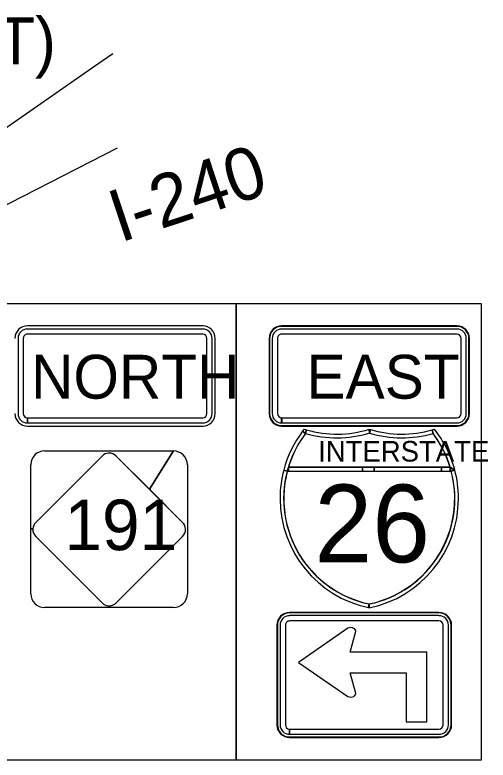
# Model space of a CAD drawing. Extents: x 886234 to 968767, y 455416 to 684046.
# Drawn here: x 919925 to 921059, y 516776 to 518560 of the extents above; entities that cross this region are included whole.
import ezdxf

# ---------------------------------------------------------------- set-up
doc = ezdxf.new("R2010")
doc.units = 0
for name, color, linetype in [('TC CONSTRUCTION PROPOSED ROADWAY SHADE', 7, 'Continuous'), ('TC DEV SIGN BLACK 239', 7, 'Continuous'), ('TC DEV SIGN BLACK ZERO', 7, 'Continuous'), ('TC DEV SIGN WHITE', 7, 'Continuous'), ('TC LABEL TEXT', 7, 'Continuous')]:
    doc.layers.add(name, color=color, linetype=linetype)

msp = doc.modelspace()

# ---------------------------------------------------------------- linework, layer by layer
at = {"layer": 'TC CONSTRUCTION PROPOSED ROADWAY SHADE'}
msp.add_lwpolyline([(920455, 517868.9), (921042.7, 517868.9), (921042.7, 516775.8), (920455, 516775.8)], close=True, dxfattribs=at)
at = {"layer": 'TC DEV SIGN BLACK 239'}
for p, q in [((920375.2, 517808), (919955.2, 517808)), ((920375.2, 517808), (919955.2, 517808)), ((920984.3, 517808), (920564.3, 517808)), ((919932.7, 517785.5), (919932.7, 517605.5)), ((919932.7, 517785.5), (919932.7, 517605.5)), ((919945.2, 517785.5), (919945.2, 517605.5)), ((919945.2, 517785.5), (919945.2, 517605.5)), ((920375.2, 517795.5), (919955.2, 517795.5)), ((920375.2, 517795.5), (919955.2, 517795.5)), ((920385.2, 517605.5), (920385.2, 517785.5)), ((920385.2, 517605.5), (920385.2, 517785.5)), ((920397.7, 517605.5), (920397.7, 517785.5)), ((920397.7, 517605.5), (920397.7, 517785.5)), ((920541.8, 517785.5), (920541.8, 517605.5)), ((920554.3, 517785.5), (920554.3, 517605.5)), ((920984.3, 517795.5), (920564.3, 517795.5)), ((920994.3, 517605.5), (920994.3, 517785.5)), ((921006.8, 517605.5), (921006.8, 517785.5)), ((919955.2, 517583), (919955.2, 517595.5)), ((919955.2, 517583), (919955.2, 517595.5)), ((919955.3, 517595.5), (920375.2, 517595.5)), ((919955.3, 517595.5), (919955.3, 517583)), ((919955.3, 517595.5), (920375.2, 517595.5)), ((919955.3, 517595.5), (919955.3, 517583)), ((920564.3, 517583), (920564.3, 517595.5)), ((920564.4, 517595.5), (920984.3, 517595.5)), ((920564.4, 517595.5), (920564.4, 517583)), ((919955.3, 517583), (920375.2, 517583)), ((919955.3, 517583), (920375.2, 517583)), ((920564.4, 517583), (920984.3, 517583)), ((919996.5, 517516.1), (920150.9, 517516.1)), ((919996.5, 517516.1), (919996.5, 517516.1)), ((919996.5, 517516.1), (920305.3, 517516.1)), ((919996.5, 517516.1), (919996.5, 517516.1)), ((920150.9, 517516.1), (920305.3, 517516.1)), ((920247.6, 517424.4), (920305.3, 517516.1)), ((920134.1, 517503.8), (919975.3, 517345)), ((919963.4, 517329.5), (919963.4, 517483)), ((919963.4, 517329.5), (919963.4, 517483)), ((920338.4, 517483), (920338.4, 517174.2)), ((920338.4, 517483), (920338.4, 517174.2)), ((920327, 517345), (920247.6, 517424.4)), ((919968.3, 517329.5), (919963.4, 517329.5)), ((919963.4, 517329.4), (919968.3, 517329.4)), ((919963.4, 517174.2), (919963.4, 517329.4)), ((919963.4, 517174.2), (919963.4, 517329.4)), ((919975.3, 517311), (920134.1, 517152.2)), ((920168.2, 517152.2), (920327, 517311)), ((920305.3, 517141.1), (919996.5, 517141.1)), ((920150.9, 517141.1), (919996.5, 517141.1)), ((920305.3, 517141.1), (920150.9, 517141.1)), ((920941.2, 517121.7), (920583.4, 517121.7)), ((920941.2, 517109), (920583.4, 517109)), ((920560.6, 517098.8), (920560.6, 516860.3)), ((920573.3, 517098.8), (920573.3, 516860.3)), ((920723.1, 517091.5), (920604.5, 517009.8)), ((920951.3, 516860.3), (920951.3, 517098.8)), ((920964, 516860.3), (920964, 517098.8)), ((920728.3, 517034.2), (920741.6, 517081.5)), ((920912.5, 517034.2), (920728.3, 517034.2)), ((920912.5, 516867.2), (920912.5, 517034.2)), ((920604.5, 517009.8), (920723.1, 516928.2)), ((920741.6, 516938.1), (920728.2, 516984.6)), ((920728.2, 516984.6), (920863, 516984.6)), ((920863, 516984.6), (920863, 516867.2)), ((920863, 516867.2), (920912.5, 516867.2)), ((920583.4, 516837.5), (920583.4, 516850.2)), ((920583.5, 516850.2), (920941.2, 516850.2)), ((920583.5, 516850.2), (920583.5, 516837.5)), ((920583.5, 516837.5), (920941.2, 516837.5))]:
    msp.add_line(p, q, dxfattribs=at)
msp.add_lwpolyline([(920305.3, 517516.1), (920247.6, 517424.4), (920168.2, 517503.8)], dxfattribs=at)
for centre, radius, start, end in [((919996.5, 517483), 33.1, 90, 180), ((919996.5, 517483), 33.1, 90, 180), ((920305.3, 517483), 33.1, 360, 90), ((920305.3, 517483), 33.1, 360, 90), ((920151.1, 517486.8), 24.1, 93.2102, 135), ((920151.1, 517486.8), 24.1, 45, 93.0763), ((919992.3, 517328), 24.1, 135, 176.407), ((920310, 517328), 24.1, 1.9293, 45), ((919992.3, 517328), 24.1, 176.5595, 225), ((920310, 517328), 24.1, 315, 1.7382), ((919996.5, 517174.2), 33.1, 180, 270), ((919996.5, 517174.2), 33.1, 180, 270), ((920305.3, 517174.2), 33.1, 270, 360), ((920305.3, 517174.2), 33.1, 270, 360), ((920151.1, 517169.2), 24.1, 225, 265.0473), ((920151.1, 517169.2), 24.1, 265.1815, 315)]:
    msp.add_arc(centre, radius, start, end, dxfattribs=at)
for centre, major_axis, ratio, start_param, end_param in [((919955.2, 517785.5), (22.5, 0), 0.999865, 1.570796, 3.141593), ((919955.2, 517785.5), (22.5, 0), 0.999865, 1.570796, 3.141593), ((920375.2, 517785.5), (22.5, 0), 0.999865, 0, 1.570796), ((920375.2, 517785.5), (22.5, 0), 0.999865, 0, 1.570796), ((920564.3, 517785.5), (22.5, 0), 0.999865, 1.570796, 3.141593), ((920984.3, 517785.5), (22.5, 0), 0.999865, 0, 1.570796), ((919955.2, 517785.5), (10, 0), 0.999865, 1.570796, 3.141593), ((919955.2, 517785.5), (10, 0), 0.999865, 1.570796, 3.141593), ((920375.2, 517785.5), (10, 0), 0.999865, 0, 1.570796), ((920375.2, 517785.5), (10, 0), 0.999865, 0, 1.570796), ((920564.3, 517785.5), (10, 0), 0.999865, 1.570796, 3.141593), ((920984.3, 517785.5), (10, 0), 0.999865, 0, 1.570796), ((919955.2, 517605.5), (22.5, 0), 0.999865, 3.141593, 4.712389), ((919955.2, 517605.5), (22.5, 0), 0.999865, 3.141593, 4.712389), ((919955.2, 517605.5), (10, 0), 0.999865, 3.141593, 4.712389), ((919955.2, 517605.5), (10, 0), 0.999865, 3.141593, 4.712389), ((920375.2, 517605.5), (22.5, 0), 0.999865, 4.712389, 6.283185), ((920375.2, 517605.5), (10, 0), 0.999865, 4.712389, 6.283185), ((920375.2, 517605.5), (22.5, 0), 0.999865, 4.712389, 6.283185), ((920375.2, 517605.5), (10, 0), 0.999865, 4.712389, 6.283185), ((920564.3, 517605.5), (22.5, 0), 0.999865, 3.141593, 4.712389), ((920564.3, 517605.5), (10, 0), 0.999865, 3.141593, 4.712389), ((920984.3, 517605.5), (22.5, 0), 0.999865, 4.712389, 6.283185), ((920984.3, 517605.5), (10, 0), 0.999865, 4.712389, 6.283185), ((920583.4, 517098.8), (22.8, 0), 0.999865, 1.570796, 3.141593), ((920583.4, 517098.8), (10.1, 0), 0.999865, 1.570796, 3.141593), ((920941.2, 517098.8), (22.8, 0), 0.999865, 0, 1.570796), ((920941.2, 517098.8), (10.1, 0), 0.999865, 0, 1.570796), ((920730, 517084.2), (-12.2, 0), 0.720018, 2.830617, 5.313577), ((920730, 516935.4), (-12.2, 0), 0.720018, 0.96961, 3.452569), ((920583.4, 516860.3), (22.8, 0), 0.999865, 3.141593, 4.712389), ((920583.4, 516860.3), (10.1, 0), 0.999865, 3.141593, 4.712389), ((920941.2, 516860.3), (22.8, 0), 0.999865, 4.712389, 6.283185), ((920941.2, 516860.3), (10.1, 0), 0.999865, 4.712389, 6.283185)]:
    msp.add_ellipse(centre, major_axis=major_axis, ratio=ratio, start_param=start_param, end_param=end_param, dxfattribs=at)
at = {"layer": 'TC DEV SIGN BLACK ZERO'}
for p, q in [((920984.3, 517815.5), (920564.3, 517815.5)), ((920564.3, 517814.2), (920564.3, 517814.3)), ((920984.3, 517814.2), (920564.3, 517814.3)), ((920984.3, 517814.2), (920984.3, 517814.2)), ((920534.2, 517785.5), (920534.2, 517605.5)), ((920535.5, 517785.5), (920535.5, 517605.5)), ((920535.5, 517785.5), (920535.5, 517785.5)), ((921013.1, 517785.5), (921013.1, 517785.5)), ((921013.1, 517605.5), (921013.1, 517785.5)), ((921014.3, 517605.5), (921014.3, 517785.5)), ((920535.5, 517605.5), (920535.5, 517605.5)), ((921013.1, 517605.5), (921013.1, 517605.5)), ((920564.3, 517575.5), (920564.3, 517576.8)), ((920564.3, 517576.8), (920564.3, 517576.7)), ((920564.3, 517576.8), (920984.3, 517576.8)), ((920564.3, 517576.8), (920564.3, 517575.5)), ((920564.3, 517575.5), (920984.3, 517575.5)), ((920984.3, 517576.7), (920984.3, 517576.8)), ((920621.4, 517557.7), (920623.8, 517566.3)), ((920774.5, 517558.7), (920774.2, 517568)), ((920774.5, 517559.4), (920774.2, 517568)), ((920924.7, 517566.3), (920927.1, 517557.7)), ((920577.9, 517467.9), (920970.6, 517467.9)), ((920577.9, 517467.9), (920580.4, 517467.9)), ((920580.4, 517476.8), (920968.1, 517476.8)), ((920757.9, 517476.8), (920580.4, 517476.8)), ((920580.4, 517467.9), (920757.9, 517467.9)), ((920786.1, 517476.8), (920757.9, 517476.8)), ((920757.9, 517467.9), (920786.1, 517467.9)), ((920947.1, 517476.8), (920786.1, 517476.8)), ((920786.1, 517467.9), (920947.1, 517467.9)), ((920968.1, 517476.8), (920947.1, 517476.8)), ((920947.1, 517467.9), (920968.1, 517467.9)), ((920979.2, 517470.2), (920968.1, 517476.8)), ((920970.4, 517468.6), (920968.1, 517467.9)), ((920968.1, 517467.9), (920970.6, 517467.9)), ((920560.5, 517403.6), (920560.5, 517401)), ((920988, 517400.9), (920988, 517403.7)), ((920774.2, 517140.5), (920774.2, 517149.6)), ((920941.2, 517129.3), (920583.4, 517129.3)), ((920583.4, 517128), (920583.4, 517128)), ((920941.2, 517128), (920583.4, 517128)), ((920941.2, 517128), (920941.2, 517128)), ((920553, 517098.8), (920553, 516860.3)), ((920554.3, 517098.8), (920554.2, 516860.3)), ((920554.3, 517098.8), (920554.3, 517098.8)), ((920970.4, 517098.8), (920970.4, 517098.8)), ((920970.4, 516860.3), (920970.4, 517098.8)), ((920971.6, 516860.3), (920971.6, 517098.8)), ((920554.3, 516860.3), (920554.2, 516860.3)), ((920970.4, 516860.3), (920970.3, 516860.3)), ((920583.4, 516829.9), (920583.4, 516831.2)), ((920583.4, 516831.2), (920583.4, 516831.1)), ((920583.4, 516831.2), (920941.2, 516831.2)), ((920583.4, 516831.2), (920583.4, 516829.9)), ((920583.4, 516829.9), (920941.2, 516829.9)), ((920941.2, 516831.1), (920941.2, 516831.2))]:
    msp.add_line(p, q, dxfattribs=at)
for points in [[(920614.3, 517563.1), (920621.4, 517557.7)], [(920621.4, 517557.7), (920614.3, 517563.1)], [(920618.1, 517568), (920618.1, 517568), (920618.1, 517568)], [(920623.8, 517566.3), (920621.4, 517557.7)], [(920774.2, 517558.7), (920774.5, 517559.4)], [(920774.5, 517567.9), (920774.5, 517559.4), (920777, 517567.2)], [(920777, 517567.2), (920774.5, 517558.7)], [(920927.1, 517557.7), (920924.7, 517566.3)], [(920930.4, 517568), (920930.4, 517568), (920930.4, 517568)], [(920569.3, 517470.2), (920577.9, 517467.9)], [(920577.9, 517467.9), (920569.3, 517470.2)], [(920580.4, 517476.8), (920580.4, 517467.9)], [(920580.4, 517467.9), (920580.4, 517476.8)], [(920757.9, 517467.9), (920757.9, 517476.8)], [(920757.9, 517476.8), (920757.9, 517467.9)], [(920786.1, 517476.8), (920786.1, 517467.9)], [(920786.1, 517467.9), (920786.1, 517476.8)], [(920947.1, 517467.9), (920947.1, 517476.8)], [(920947.1, 517476.8), (920947.1, 517467.9)], [(920968.1, 517476.8), (920979.2, 517470.2)], [(920968.1, 517467.9), (920968.1, 517476.8)], [(920968.1, 517476.8), (920968.1, 517467.9), (920970.4, 517468.6), (920968.1, 517476.8)], [(920970.6, 517467.9), (920970.4, 517468.6)], [(920979.2, 517470.2), (920970.6, 517467.9)], [(920970.6, 517467.9), (920979.2, 517470.2)], [(920772.4, 517140.9), (920774.2, 517149.6)], [(920774.2, 517149.6), (920772.4, 517140.9), (920774.2, 517140.5)], [(920774.2, 517149.6), (920774.2, 517140.5)]]:
    msp.add_lwpolyline(points, dxfattribs=at)
for centre, radius, start, end in [((920827.7, 517402.3), 267.2, 142.9968, 165.2769), ((920827.7, 517402.3), 258.3, 142.9968, 258.0595), ((920827.7, 517402.3), 258.3, 142.9968, 165.2769), ((920827.7, 517402.3), 267.2, 141.6709, 142.9968), ((920696.2, 517823.5), 267.2, 253.0099, 254.2907), ((920696.2, 517823.5), 276.1, 254.2907, 286.4259), ((920696.2, 517823.5), 276.1, 254.2907, 286.4259), ((920696.2, 517823.5), 267.2, 254.2907, 286.9893), ((920852.3, 517823.5), 276.1, 253.5741, 285.7093), ((920720.8, 517402.3), 258.3, 281.9405, 37.0032), ((920852.3, 517823.5), 267.2, 253.0588, 253.6206), ((920852.4, 517823.1), 275.7, 253.5731, 285.7093), ((920852.3, 517823.5), 267.2, 253.6206, 285.7093), ((920852.3, 517823.5), 267.2, 285.7093, 286.9901), ((920720.8, 517402.3), 258.3, 16.7759, 37.0032), ((920720.8, 517402.3), 267.2, 14.7231, 38.3291), ((920827.7, 517402.3), 267.2, 165.2769, 179.7177), ((920826.4, 517401.5), 257.3, 165.0438, 258.3001), ((920827.7, 517402.3), 258.3, 163.2241, 165.2769), ((920722.1, 517401.5), 257.3, 281.7196, 14.964), ((920720.8, 517402.3), 258.3, 14.7231, 16.7759), ((920720.8, 517402.3), 267.2, 0.2997, 14.7231), ((920827.7, 517402.3), 267.2, 180.2823, 258.0591), ((920720.8, 517402.3), 267.2, 281.537, 359.7003), ((920720.8, 517402.3), 258.3, 281.9405, 281.9604), ((920827.7, 517402.3), 267.2, 258.458, 258.463), ((920720.8, 517402.3), 267.2, 281.5369590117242, 281.53700435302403)]:
    msp.add_arc(centre, radius, start, end, dxfattribs=at)
for centre, major_axis, start_param, end_param in [((920564.3, 517785.5), (30, 0), 1.570796, 3.141593), ((920564.3, 517785.5), (28.8, 0), 1.570796, 3.141593), ((920984.3, 517785.5), (30, 0), 0, 1.570796), ((920984.3, 517785.5), (28.8, 0), 0, 1.570796), ((920564.3, 517605.5), (30, 0), 3.141593, 4.712389), ((920564.3, 517605.5), (28.8, 0), 3.141593, 4.712389), ((920984.3, 517605.5), (30, 0), 4.712389, 6.283185), ((920984.3, 517605.5), (28.8, 0), 4.712389, 6.283185), ((920583.4, 517098.8), (30.4, 0), 1.570796, 3.141593), ((920583.4, 517098.8), (29.2, 0), 1.570796, 3.141593), ((920941.2, 517098.8), (30.4, 0), 0, 1.570796), ((920941.2, 517098.8), (29.2, 0), 0, 1.570796), ((920583.4, 516860.3), (30.4, 0), 3.141593, 4.712389), ((920583.4, 516860.3), (29.2, 0), 3.141593, 4.712389), ((920941.2, 516860.3), (30.4, 0), 4.712389, 6.283185), ((920941.2, 516860.3), (29.2, 0), 4.712389, 6.283185)]:
    msp.add_ellipse(centre, major_axis=major_axis, ratio=0.999865, start_param=start_param, end_param=end_param, dxfattribs=at)
at = {"layer": 'TC DEV SIGN WHITE'}
for p, q in [((920375.2, 517815.5), (919955.2, 517815.5)), ((920984.3, 517815.5), (920564.3, 517815.5)), ((920405.2, 517605.5), (920405.2, 517785.5)), ((920534.2, 517785.5), (920534.2, 517605.5)), ((921014.3, 517605.5), (921014.3, 517785.5)), ((919955.2, 517575.5), (920375.2, 517575.5)), ((920564.3, 517575.5), (920984.3, 517575.5)), ((919975.3, 517345), (920134.1, 517503.8)), ((920134.1, 517503.8), (919975.3, 517345)), ((920168.2, 517503.8), (920327, 517345)), ((920168.2, 517503.8), (920168.2, 517503.8)), ((920327, 517345), (920168.2, 517503.8)), ((919968.3, 517329.4), (919968.3, 517329.4)), ((920134.1, 517152.2), (919975.3, 517311)), ((919975.3, 517311), (920134.1, 517152.2)), ((920327, 517311), (920168.2, 517152.2)), ((920168.2, 517152.2), (920327, 517311)), ((920941.2, 517129.3), (920583.4, 517129.3)), ((920553, 517098.8), (920553, 516860.3)), ((920971.6, 516860.3), (920971.6, 517098.8)), ((920583.4, 516829.9), (920941.2, 516829.9))]:
    msp.add_line(p, q, dxfattribs=at)
for points in [[(920149.9, 517510.8), (920149.8, 517510.8)], [(919968.3, 517329.5), (919968.3, 517329.5), (919968.3, 517329.4)], [(920334, 517328.7), (920334, 517328.8)], [(920149.1, 517145.2), (920149.1, 517145.2)]]:
    msp.add_lwpolyline(points, dxfattribs=at)
for centre, start, end in [((920151.1, 517486.8), 93.2102, 135), ((920151.1, 517486.8), 93.2102, 135), ((920151.1, 517486.8), 45, 93.0763), ((920151.1, 517486.8), 45, 93.0763), ((919992.3, 517328), 135, 176.407), ((919992.3, 517328), 135, 176.407), ((920310, 517328), 1.9293, 45), ((920310, 517328), 1.9293, 45), ((919992.3, 517328), 176.5595, 225), ((919992.3, 517328), 176.5602, 225), ((920310, 517328), 315, 1.7382), ((920310, 517328), 315, 1.7382), ((920151.1, 517169.2), 225, 265.0473), ((920151.1, 517169.2), 225, 265.0473), ((920151.1, 517169.2), 265.1815, 315), ((920151.1, 517169.2), 265.1815, 315)]:
    msp.add_arc(centre, 24.1, start, end, dxfattribs=at)
for centre, major_axis, start_param, end_param in [((919955.2, 517785.5), (30, 0), 1.570796, 3.141593), ((920375.2, 517785.5), (30, 0), 0, 1.570796), ((920564.3, 517785.5), (30, 0), 1.570796, 3.141593), ((920984.3, 517785.5), (30, 0), 0, 1.570796), ((919955.2, 517605.5), (30, 0), 3.141593, 4.712389), ((920375.2, 517605.5), (30, 0), 4.712389, 6.283185), ((920564.3, 517605.5), (30, 0), 3.141593, 4.712389), ((920984.3, 517605.5), (30, 0), 4.712389, 6.283185), ((920583.4, 517098.8), (30.4, 0), 1.570796, 3.141593), ((920941.2, 517098.8), (30.4, 0), 0, 1.570796), ((920583.4, 516860.3), (30.4, 0), 3.141593, 4.712389), ((920941.2, 516860.3), (30.4, 0), 4.712389, 6.283185)]:
    msp.add_ellipse(centre, major_axis=major_axis, ratio=0.999865, start_param=start_param, end_param=end_param, dxfattribs=at)
at = {"layer": 'TC LABEL TEXT'}
for points in [[(920160.1, 518467.2), (920110.8, 518433.6), (919889.3, 518279.6), (919578.1, 518083.4)], [(919202.3, 517746.1), (920170.9, 518242)]]:
    msp.add_lwpolyline(points, dxfattribs=at)
for points in [[(919867.3, 517868.9), (920455, 517868.9), (920455, 516775.8), (919867.3, 516775.8)], [(920455, 517868.9), (921042.7, 517868.9), (921042.7, 516775.8), (920455, 516775.8)]]:
    msp.add_lwpolyline(points, close=True, dxfattribs=at)

# ---------------------------------------------------------------- texts
at = {"layer": 'TC DEV SIGN BLACK 239'}
for s, height, p in [('NORTH', 105, (919963.9, 517641.2)), ('EAST', 105, (920623.9, 517641.2)), ('191', 120.97, (920044, 517278.5))]:
    msp.add_text(s, height=height, rotation=360, dxfattribs=at).set_placement(p)
at = {"layer": 'TC DEV SIGN BLACK ZERO'}
for s, height, p in [('INTERSTATE', 49.28, (920651.8, 517490.6)), ('26', 186.16, (920642.9, 517249.3))]:
    msp.add_text(s, height=height, rotation=360, dxfattribs=at).set_placement(p)
at = {"layer": 'TC LABEL TEXT'}
msp.add_text('(EXIST)', height=112.5, dxfattribs=at).set_placement((919488.6, 518441.7))
msp.add_text('I-240', height=125, rotation=18.3431, dxfattribs=at).set_placement((920176.9, 518014.4))

doc.saveas('drawing.dxf')
